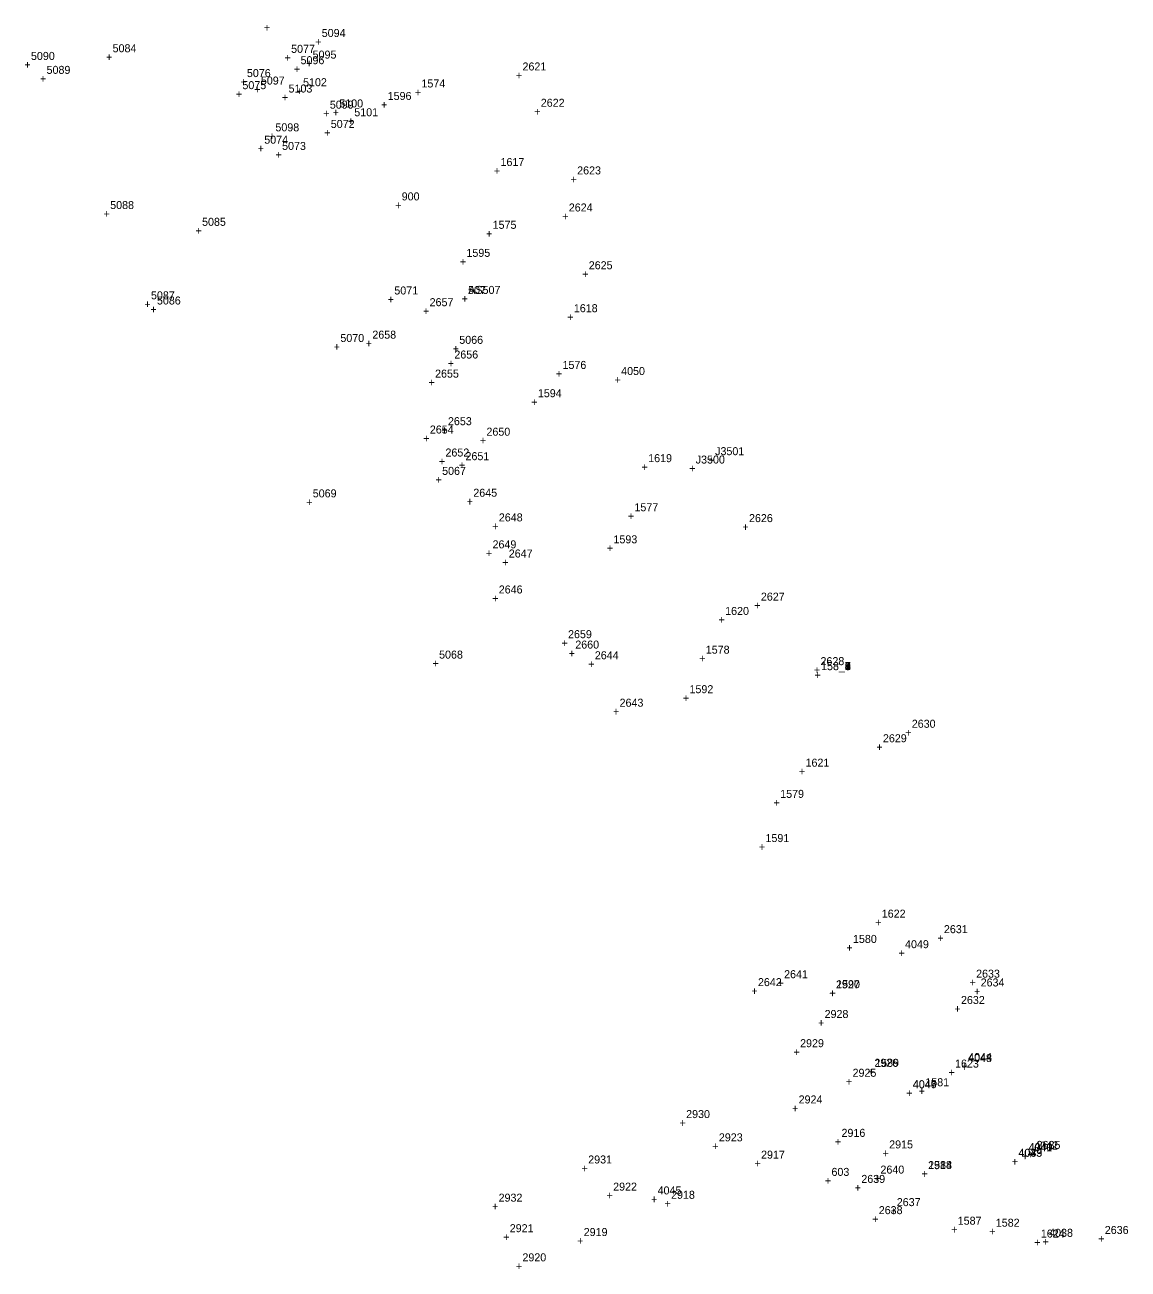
# Model space of a CAD drawing. Extents: x 1036751 to 1042192, y 772604 to 785439.
# Drawn here: x 1039042.9 to 1039387.6, y 777008.1 to 777396.8 of the extents above; entities that cross this region are included whole.
import ezdxf

# ---------------------------------------------------------------- set-up
doc = ezdxf.new("R2010")
doc.units = 0
for name, color, linetype in [('S_Control_Temp_Traverse', 7, 'Continuous'), ('S_Control_Traverse_Point', 7, 'Continuous'), ('S_Ground_Elevation', 7, 'Continuous'), ('S_Ground_LevelString', 7, 'Continuous'), ('S_Property_IronPipeFound', 7, 'Continuous'), ('S_Property_Mailbox', 7, 'Continuous'), ('S_Roadway_Centerline', 7, 'Continuous'), ('S_Roadway_Drive_Gravel', 7, 'Continuous'), ('S_Roadway_Edge_Pavement', 7, 'Continuous'), ('S_Traffic_Sign_DoublePost', 7, 'Continuous'), ('S_Traffic_Sign_SinglePost', 7, 'Continuous'), ('S_Trees_Conifer_NonPay', 7, 'Continuous'), ('S_Trees_Conifer_Pay', 7, 'Continuous'), ('S_Trees_Decid_NonPay', 7, 'Continuous'), ('S_Trees_Decid_Pay', 7, 'Continuous'), ('S_Utilities_GuyWire3', 7, 'Continuous'), ('S_Utilities_Hydrant', 7, 'Continuous'), ('S_Utilities_Pole_Brace3', 7, 'Continuous'), ('S_Utilities_Pole_Power', 7, 'Continuous'), ('S_Utilities_UG_Water_Gate', 7, 'Continuous'), ('S_Utilities_UG_Water_Line', 7, 'Continuous'), ('S_Utilities_UG_Water_Shutoff', 7, 'Continuous')]:
    doc.layers.add(name, color=color, linetype=linetype)

msp = doc.modelspace()

# ---------------------------------------------------------------- texts
at = {"layer": 'S_Control_Temp_Traverse'}
for s, p in [('+', (1039158.57, 777339.24)), ('+', (1039158.57, 777339.24)), ('+', (1039158.57, 777339.24)), ('900', (1039160.63, 777341.99)), ('900', (1039160.63, 777341.99)), ('900', (1039160.63, 777341.99)), ('158', (1039291.66, 777195.24)), ('158_9', (1039291.65, 777195.24)), ('158_8', (1039291.65, 777195.24)), ('158_1', (1039291.65, 777195.24)), ('158_3', (1039291.65, 777195.24)), ('158_2', (1039291.65, 777195.24)), ('158_5', (1039291.65, 777195.24)), ('158_4', (1039291.65, 777195.24)), ('158_7', (1039291.65, 777195.24)), ('158_6', (1039291.65, 777195.24)), ('+', (1039289.59, 777192.49)), ('+', (1039289.59, 777192.49)), ('+', (1039289.59, 777192.49)), ('+', (1039289.59, 777192.49)), ('+', (1039289.59, 777192.49)), ('+', (1039289.59, 777192.49)), ('+', (1039289.59, 777192.49)), ('+', (1039289.59, 777192.49)), ('+', (1039289.59, 777192.49)), ('+', (1039289.59, 777192.49)), ('603', (1039294.9, 777037.25)), ('603', (1039294.9, 777037.25)), ('603', (1039294.9, 777037.25)), ('603', (1039294.9, 777037.25)), ('603', (1039294.9, 777037.25)), ('603', (1039294.9, 777037.25)), ('603', (1039294.9, 777037.25)), ('+', (1039292.84, 777034.5)), ('+', (1039292.84, 777034.5)), ('+', (1039292.84, 777034.5)), ('+', (1039292.84, 777034.5)), ('+', (1039292.84, 777034.5)), ('+', (1039292.84, 777034.5)), ('+', (1039292.84, 777034.5))]:
    msp.add_text(s, height=2.5, dxfattribs=at).set_placement(p)
at = {"layer": 'S_Control_Traverse_Point'}
for s, p in [('AS507', (1039181.44, 777312.78)), ('507', (1039181.37, 777312.74)), ('507', (1039181.37, 777312.74)), ('507', (1039181.37, 777312.74)), ('507', (1039181.37, 777312.74)), ('507', (1039181.37, 777312.74)), ('507', (1039181.37, 777312.74)), ('507', (1039181.37, 777312.74)), ('507', (1039181.37, 777312.74)), ('+', (1039179.31, 777309.99)), ('+', (1039179.31, 777309.99)), ('+', (1039179.31, 777309.99)), ('+', (1039179.31, 777309.99)), ('+', (1039179.31, 777309.99)), ('+', (1039179.31, 777309.99)), ('+', (1039179.31, 777309.99)), ('+', (1039179.31, 777309.99)), ('+', (1039179.38, 777310.03))]:
    msp.add_text(s, height=2.5, dxfattribs=at).set_placement(p)
at = {"layer": 'S_Ground_Elevation'}
for s, p in [('+', (1039117.58, 777394.72)), ('+', (1039133.59, 777390.29)), ('5094', (1039135.65, 777393.04)), ('5077', (1039126.08, 777388.09)), ('5095', (1039132.8, 777386.29)), ('5089', (1039049.68, 777381.52)), ('+', (1039124.02, 777385.34)), ('5096', (1039129.03, 777384.54)), ('+', (1039130.74, 777383.54)), ('+', (1039047.62, 777378.77)), ('5076', (1039112.27, 777380.52)), ('5097', (1039116.63, 777378.18)), ('+', (1039126.97, 777381.79)), ('+', (1039110.21, 777377.77)), ('5075', (1039110.86, 777376.74)), ('+', (1039114.57, 777375.43)), ('+', (1039108.8, 777373.99)), ('5099', (1039138.17, 777370.65)), ('5100', (1039141.13, 777371.04)), ('+', (1039136.11, 777367.9)), ('+', (1039139.07, 777368.29)), ('5101', (1039145.82, 777368.28)), ('5098', (1039121.17, 777363.57)), ('5072', (1039138.47, 777364.62)), ('+', (1039143.76, 777365.53)), ('5074', (1039117.69, 777359.7)), ('+', (1039119.11, 777360.82)), ('+', (1039136.41, 777361.87)), ('+', (1039115.63, 777356.95)), ('+', (1039121.2, 777355)), ('5073', (1039123.26, 777357.75)), ('5088', (1039069.55, 777339.29)), ('+', (1039067.48, 777336.54)), ('5071', (1039158.33, 777312.6)), ('+', (1039080.24, 777308.34)), ('5087', (1039082.3, 777311.09)), ('+', (1039156.27, 777309.85)), ('5070', (1039141.47, 777297.76)), ('5066', (1039178.62, 777297.18)), ('+', (1039139.4, 777295.01)), ('+', (1039176.56, 777294.43)), ('5067', (1039173.26, 777256.25)), ('+', (1039171.19, 777253.5)), ('+', (1039130.78, 777246.47)), ('5069', (1039132.84, 777249.22)), ('5068', (1039172.31, 777198.85)), ('+', (1039170.25, 777196.1))]:
    msp.add_text(s, height=2.5, dxfattribs=at).set_placement(p)
at = {"layer": 'S_Ground_LevelString'}
for s, p in [('1590', (1039296.36, 777095.9)), ('+', (1039294.29, 777093.15)), ('1589', (1039308.56, 777071.32)), ('+', (1039306.5, 777068.57))]:
    msp.add_text(s, height=2.5, dxfattribs=at).set_placement(p)
at = {"layer": 'S_Property_IronPipeFound'}
for s, p in [('+', (1039213.39, 777347.36)), ('2623', (1039215.45, 777350.11)), ('4050', (1039229.19, 777287.44)), ('+', (1039227.13, 777284.69)), ('+', (1039218.91, 777195.89)), ('2644', (1039220.97, 777198.64))]:
    msp.add_text(s, height=2.5, dxfattribs=at).set_placement(p)
at = {"layer": 'S_Property_Mailbox'}
for s, p in [('2625', (1039219.07, 777320.48)), ('+', (1039217.01, 777317.73))]:
    msp.add_text(s, height=2.5, dxfattribs=at).set_placement(p)
at = {"layer": 'S_Roadway_Centerline'}
for s, p in [('+', (1039164.74, 777374.52)), ('1574', (1039166.8, 777377.27)), ('1575', (1039189.04, 777333.11)), ('+', (1039186.98, 777330.36)), ('1576', (1039210.87, 777289.34)), ('+', (1039208.81, 777286.59)), ('+', (1039231.28, 777242.13)), ('1577', (1039233.34, 777244.88)), ('1578', (1039255.63, 777200.39)), ('+', (1039253.57, 777197.64)), ('1579', (1039278.88, 777155.35)), ('+', (1039276.82, 777152.6)), ('1580', (1039301.62, 777110.03)), ('+', (1039299.56, 777107.28)), ('2926', (1039308.31, 777071.33)), ('2925', (1039301.49, 777068.22)), ('+', (1039306.25, 777068.58)), ('+', (1039299.43, 777065.47)), ('1581', (1039324.22, 777065.26)), ('2924', (1039284.64, 777059.89)), ('+', (1039322.16, 777062.51)), ('+', (1039282.58, 777057.14)), ('2923', (1039259.72, 777048.04)), ('+', (1039257.66, 777045.29)), ('2922', (1039226.69, 777032.64)), ('+', (1039224.63, 777029.89)), ('1582', (1039346.24, 777021.38)), ('+', (1039192.32, 777016.91)), ('2921', (1039194.38, 777019.66)), ('+', (1039344.18, 777018.63))]:
    msp.add_text(s, height=2.5, dxfattribs=at).set_placement(p)
at = {"layer": 'S_Roadway_Drive_Gravel'}
for s, p in [('5090', (1039044.8, 777385.87)), ('5084', (1039070.31, 777388.27)), ('+', (1039042.74, 777383.12)), ('+', (1039068.25, 777385.52)), ('5085', (1039098.26, 777334.05)), ('+', (1039096.2, 777331.3)), ('5086', (1039084.16, 777309.47)), ('+', (1039082.1, 777306.72))]:
    msp.add_text(s, height=2.5, dxfattribs=at).set_placement(p)
at = {"layer": 'S_Roadway_Edge_Pavement'}
for s, p in [('+', (1039154.19, 777370.62)), ('1596', (1039156.25, 777373.37)), ('1617', (1039191.5, 777352.73)), ('+', (1039189.44, 777349.98)), ('1595', (1039180.85, 777324.36)), ('+', (1039178.79, 777321.61)), ('+', (1039212.35, 777304.32)), ('1618', (1039214.41, 777307.07)), ('1594', (1039203.17, 777280.51)), ('+', (1039201.11, 777277.76)), ('1619', (1039237.64, 777260.22)), ('+', (1039235.58, 777257.47)), ('1593', (1039226.79, 777234.87)), ('+', (1039224.73, 777232.12)), ('1620', (1039261.69, 777212.48)), ('+', (1039259.63, 777209.73)), ('1592', (1039250.54, 777188.05)), ('+', (1039248.48, 777185.3)), ('1621', (1039286.8, 777165.09)), ('+', (1039284.74, 777162.34)), ('1591', (1039274.28, 777141.54)), ('+', (1039272.22, 777138.79)), ('1622', (1039310.61, 777117.92)), ('+', (1039308.55, 777115.17)), ('2927', (1039296.28, 777095.82)), ('+', (1039294.21, 777093.07)), ('2928', (1039292.75, 777086.57)), ('+', (1039290.69, 777083.82)), ('2929', (1039285.1, 777077.46)), ('+', (1039283.04, 777074.71)), ('1623', (1039333.51, 777071.09)), ('+', (1039331.45, 777068.34)), ('2930', (1039249.5, 777055.32)), ('+', (1039247.44, 777052.57)), ('2916', (1039298.04, 777049.45)), ('+', (1039295.97, 777046.7)), ('2915', (1039312.93, 777045.84)), ('2931', (1039218.9, 777041.13)), ('2917', (1039272.9, 777042.63)), ('+', (1039310.87, 777043.09)), ('+', (1039216.84, 777038.38)), ('+', (1039270.84, 777039.88)), ('+', (1039323.02, 777036.61)), ('+', (1039323.05, 777036.67)), ('2914', (1039325.08, 777039.36)), ('1588', (1039325.11, 777039.42)), ('2932', (1039190.9, 777029.2)), ('2918', (1039244.79, 777030.1)), ('+', (1039188.84, 777026.45)), ('+', (1039242.73, 777027.35)), ('1587', (1039334.34, 777022)), ('2919', (1039217.49, 777018.46)), ('+', (1039332.28, 777019.25)), ('1624', (1039360.32, 777017.99)), ('+', (1039215.43, 777015.71)), ('+', (1039358.26, 777015.24)), ('2920', (1039198.35, 777010.56)), ('+', (1039196.29, 777007.81))]:
    msp.add_text(s, height=2.5, dxfattribs=at).set_placement(p)
at = {"layer": 'S_Traffic_Sign_DoublePost'}
for s, p in [('5102', (1039129.81, 777377.66)), ('5103', (1039125.28, 777375.69)), ('+', (1039127.75, 777374.91)), ('+', (1039123.22, 777372.94)), ('J3501', (1039258.55, 777262.4)), ('J3500', (1039252.49, 777259.78)), ('+', (1039256.49, 777259.65)), ('+', (1039250.43, 777257.03)), ('2630', (1039319.99, 777177.25)), ('2629', (1039310.98, 777172.72)), ('+', (1039317.92, 777174.5)), ('+', (1039308.92, 777169.97)), ('2641', (1039280.1, 777099.01)), ('2642', (1039271.93, 777096.53)), ('+', (1039278.04, 777096.26)), ('+', (1039269.87, 777093.78)), ('2637', (1039315.3, 777027.81)), ('2638', (1039309.67, 777025.3)), ('+', (1039313.24, 777025.06)), ('+', (1039307.61, 777022.55))]:
    msp.add_text(s, height=2.5, dxfattribs=at).set_placement(p)
at = {"layer": 'S_Traffic_Sign_SinglePost'}
for s, p in [('2640', (1039310.2, 777037.97)), ('+', (1039302.17, 777032.31)), ('2639', (1039304.23, 777035.06)), ('+', (1039308.14, 777035.22))]:
    msp.add_text(s, height=2.5, dxfattribs=at).set_placement(p)
at = {"layer": 'S_Trees_Conifer_NonPay'}
for s, p in [('2654', (1039169.42, 777269.16)), ('+', (1039167.36, 777266.41)), ('+', (1039178.5, 777258.09)), ('2651', (1039180.56, 777260.84)), ('+', (1039186.95, 777230.54)), ('2649', (1039189.01, 777233.29)), ('2659', (1039212.6, 777205.23)), ('+', (1039210.54, 777202.48))]:
    msp.add_text(s, height=2.5, dxfattribs=at).set_placement(p)
at = {"layer": 'S_Trees_Conifer_Pay'}
for s, p in [('2621', (1039198.37, 777382.58)), ('+', (1039196.31, 777379.83)), ('2622', (1039204.08, 777371.24)), ('+', (1039202.02, 777368.49)), ('2657', (1039169.35, 777308.94)), ('+', (1039167.28, 777306.19)), ('2658', (1039151.45, 777298.79)), ('+', (1039149.39, 777296.04)), ('2656', (1039177.08, 777292.59)), ('+', (1039175.02, 777289.84)), ('2655', (1039171.06, 777286.63)), ('+', (1039169, 777283.88)), ('2653', (1039175.08, 777271.77)), ('+', (1039173.02, 777269.02)), ('+', (1039185.05, 777265.73)), ('2650', (1039187.11, 777268.48)), ('2645', (1039183, 777249.42)), ('+', (1039180.93, 777246.67)), ('2646', (1039190.95, 777219.19)), ('+', (1039188.89, 777216.44))]:
    msp.add_text(s, height=2.5, dxfattribs=at).set_placement(p)
at = {"layer": 'S_Trees_Decid_NonPay'}
for s, p in [('2652', (1039174.3, 777261.98)), ('+', (1039172.24, 777259.23)), ('2648', (1039190.98, 777241.71)), ('+', (1039188.92, 777238.96)), ('2647', (1039194.08, 777230.43)), ('+', (1039192.02, 777227.68)), ('2660', (1039214.86, 777201.98)), ('+', (1039212.8, 777199.23))]:
    msp.add_text(s, height=2.5, dxfattribs=at).set_placement(p)
at = {"layer": 'S_Trees_Decid_Pay'}
for s, p in [('+', (1039267.06, 777238.74)), ('2626', (1039269.13, 777241.49)), ('2628', (1039291.47, 777196.81)), ('+', (1039289.41, 777194.06)), ('2636', (1039380.29, 777019.11)), ('+', (1039378.23, 777016.36))]:
    msp.add_text(s, height=2.5, dxfattribs=at).set_placement(p)
at = {"layer": 'S_Utilities_GuyWire3'}
for s, p in [('2634', (1039341.51, 777096.44)), ('+', (1039339.45, 777093.69))]:
    msp.add_text(s, height=2.5, dxfattribs=at).set_placement(p)
at = {"layer": 'S_Utilities_Hydrant'}
for s, p in [('2635', (1039358.99, 777045.68)), ('+', (1039356.92, 777042.93))]:
    msp.add_text(s, height=2.5, dxfattribs=at).set_placement(p)
at = {"layer": 'S_Utilities_Pole_Brace3'}
for s, p in [('2633', (1039340.09, 777099.17)), ('+', (1039338.03, 777096.42))]:
    msp.add_text(s, height=2.5, dxfattribs=at).set_placement(p)
at = {"layer": 'S_Utilities_Pole_Power'}
for s, p in [('+', (1039210.77, 777335.78)), ('2624', (1039212.83, 777338.53)), ('2627', (1039272.85, 777216.96)), ('+', (1039270.79, 777214.21)), ('2643', (1039228.7, 777183.82)), ('+', (1039226.64, 777181.07)), ('2632', (1039335.36, 777090.95)), ('+', (1039333.3, 777088.2))]:
    msp.add_text(s, height=2.5, dxfattribs=at).set_placement(p)
at = {"layer": 'S_Utilities_UG_Water_Gate'}
for s, p in [('4047', (1039320.34, 777064.61)), ('+', (1039318.28, 777061.86)), ('4041', (1039356.45, 777044.9)), ('+', (1039354.39, 777042.15))]:
    msp.add_text(s, height=2.5, dxfattribs=at).set_placement(p)
at = {"layer": 'S_Utilities_UG_Water_Line'}
for s, p in [('4049', (1039317.89, 777108.39)), ('+', (1039315.83, 777105.64)), ('4048', (1039337.6, 777072.81)), ('4044', (1039337.62, 777073.13)), ('+', (1039335.54, 777070.06)), ('+', (1039335.56, 777070.38)), ('4046', (1039320.31, 777064.66)), ('+', (1039318.25, 777061.91)), ('4040', (1039356.49, 777044.99)), ('4042', (1039358.23, 777045.47)), ('+', (1039351.22, 777040.47)), ('+', (1039351.28, 777040.48)), ('4043', (1039353.28, 777043.22)), ('4039', (1039353.34, 777043.23)), ('+', (1039354.43, 777042.24)), ('+', (1039356.17, 777042.72)), ('+', (1039238.52, 777028.72)), ('4045', (1039240.58, 777031.47)), ('4038', (1039362.91, 777018.22)), ('+', (1039360.85, 777015.47))]:
    msp.add_text(s, height=2.5, dxfattribs=at).set_placement(p)
at = {"layer": 'S_Utilities_UG_Water_Shutoff'}
for s, p in [('+', (1039327.97, 777110.33)), ('2631', (1039330.03, 777113.08))]:
    msp.add_text(s, height=2.5, dxfattribs=at).set_placement(p)

doc.saveas('drawing.dxf')
